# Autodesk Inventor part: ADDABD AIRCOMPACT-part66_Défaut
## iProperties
Shininess: 64.0
Length Units: 11269
Angle Units: 11279
Time Units: 11290
Mass Units: 11283
Length Display Precision: 3
Angle Display Precision: 2
Compacted: True
Part Number: ADDABD AIRCOMPACT-part66_Défaut
Document SubType Name: Modeling
Created: 2006-01
Material: Par défaut
Designer: riri
Density: 0.0
Volumn: 0.0
Area: 0.0
PropertySet Name: Model Information
Control State: 0
Master: False
Checked Out: False
Author: riri
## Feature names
1. Base1
